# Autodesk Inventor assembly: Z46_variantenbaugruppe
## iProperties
Author: Schneider
Created: 2002-08
Part Number: Z46_variantenbaugruppe
Document SubType Name: Baugruppe
Designer: Schneider
Control State: 0
Master: False
Checked Out: False
Last Check In By: KSO_Schneider
Last Check In Date: 2002-08-16
PropertySet Name: Design Tracking Control
Shininess: 20.0
Length Units: 11269
Angle Units: 11283
Time Units: 11279
Mass Units: 11290
Length Display Precision: 3
Angle Display Precision: 2
Compacted: True
PropertySet Name: _Private Model Information
Density: 0.0
Volumn: 0.0
Area: 0.0
PropertySet Name: Model Information
